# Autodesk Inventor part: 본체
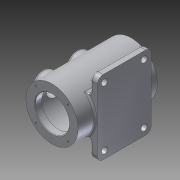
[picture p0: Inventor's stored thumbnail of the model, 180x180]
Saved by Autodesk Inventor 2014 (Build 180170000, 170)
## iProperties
Created: 2014-12
Part Number: 본체
Material: 알루미늄 6061
Document SubType Name: Modeling
Designer: Owner
Mass: 1294 g
Surface Area: 1040.12 cm^2
Volume: 477.492 cm^3
Density: 2.71 g/cm^3
Appearance: 알루미늄 - 평지
Author: Owner
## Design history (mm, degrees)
sketch "스케치1"
  geometry: C1 r 46 at (0, 0); 1 further point
  constraints: 1 centre point, 1 coincident
  dimensions: "d0" = 92 diameter of C1
extrude "돌출1" new body sketch "스케치1" stored distance "d1" = 140; taper "d2" = 0 deg
sketch "스케치2"
  geometry: C1 r 46 at (0, 0) reference; C2 r 30 at (0, 0)
  constraints: 1 centre point, 1 coincident
  dimensions: "d3" = 60 diameter of C2
extrude "돌출2" cut sketch "스케치2" distance "d4" = 12; taper "d5" = 0 deg
sketch "스케치3"
  geometry: C1 r 46 at (0, 0) reference; C2 r 30 at (0, 0)
  constraints: 1 centre point, 1 coincident
  dimensions: "d6" = 60 diameter of C2
extrude "돌출3" cut sketch "스케치3" distance "d7" = 12; taper "d8" = 0 deg
node "작업 평면2"
sketch "스케치4"
  geometry: C1 r 37.5 at (0, 0); 1 further point
  constraints: 1 centre point, 1 coincident
  dimensions: "d10" = 75 diameter of C1
extrude "돌출4" cut sketch "스케치4" stored distance "d11" = 12; taper "d12" = 0 deg
node "작업 평면3"
sketch "스케치5"
  geometry: L1 (70, -46)-(70, 46) reference; L2 (-40, 65)-(55, 65); L3 (55, 65)-(55, -65); L4 (55, -65)-(-40, -65); L5 (-40, -65)-(-40, 65); 2 further points
  constraints: 8 end point, 2 parallel, 1 horizontal, 1 horizontal alignment, 1 midpoint, 1 perpendicular
  dimensions: "d15" = 15 distance between parallel lines of L1 L3; "d16" = 130 distance between parallel lines of L4 L2; "d17" = 95 distance between parallel lines of L3 L5
extrude "돌출5" join sketch "스케치5" distance "d18" = 12; taper "d19" = 0 deg
node "작업 평면4"
sketch "스케치6"
  geometry: L1 (70, -46)-(70, 46) reference; L2 (-70, 46)-(-70, -46) reference; C1 r 20 at (30, 0); 2 further points
  constraints: 1 centre point, 1 coincident, 1 horizontal alignment
  dimensions: "d21" = 40 distance from line of L1 point (30, 0); "d22" = 40 diameter of C1
extrude "돌출6" join sketch "스케치6" stored distance "d23" = 12; taper "d24" = 0 deg
sketch "스케치7"
  geometry: L1 (-70, 46)-(-70, -46) reference; L2 (70, -46)-(70, 46) reference; C1 r 20 at (30, 0) reference; C2 r 20 at (-30, 0); 2 further points
  constraints: 1 centre point, 1 coincident, 1 horizontal alignment
  dimensions: "d25" = 60 distance of C1.centre point (-30, 0); "d26" = 40 diameter of C2
extrude "돌출7" join sketch "스케치7" stored distance "d27" = 12; taper "d28" = 0 deg
sketch "스케치8"
  geometry: C1 r 20 at (0, 0) reference; C2 r 15 at (0, 0); 1 further point
  constraints: 1 centre point, 1 coincident
  dimensions: "d29" = 30 diameter of C2
extrude "돌출8" cut sketch "스케치8" distance "d30" = 8; taper "d31" = 0 deg
sketch "스케치9"
  geometry: C1 r 20 at (0, 0) reference; C2 r 15 at (0, 0); 1 further point
  constraints: 1 centre point, 1 coincident
  dimensions: "d32" = 30 diameter of C2
extrude "돌출9" cut sketch "스케치9" distance "d33" = 8; taper "d34" = 0 deg
sketch "스케치10"
  geometry: C1 r 15 at (0, 0) reference; C2 r 12.5 at (0, 0); 1 further point
  constraints: 1 centre point, 1 coincident
  dimensions: "d35" = 25 diameter of C2
extrude "돌출10" cut sketch "스케치10" stored distance "d36" = 8; taper "d37" = 0 deg
sketch "스케치11"
  geometry: C1 r 15 at (0, 0) reference; C2 r 12.5 at (0, 0); 1 further point
  constraints: 1 centre point, 1 coincident
  dimensions: "d38" = 25 diameter of C2
extrude "돌출11" cut sketch "스케치11" stored distance "d39" = 8; taper "d40" = 0 deg
sketch "스케치12"
  geometry: L1 (0, 0)-(28.284, 28.284); L2 (0, 0)-(40, 0); C1 r 46 at (0, 0) reference; 1 further point
  constraints: 4 end point, 1 coincident, 1 equal length, 1 horizontal
  dimensions: "d41" = 40 distance of L1.start L1.end; "d42" = 45 deg angle of L2 L1
hole "구멍1" sketch "스케치12" at (28.284, 28.284) diameter "d43" = 3.242; stored, may be unused: countersink angle "d47" = 90 deg, drill point angle "d49" = 118 deg; dims "d44" = 8, "d45" = 4, "d46" = 2, "d48" = 10
fillet "모깎기1" dims "d53" = 10
sketch "스케치14"
  geometry: L1 (-25.923, 55)-(-55, 55) reference; L2 (-65, 45)-(-65, -30) reference; L3 (-55, -40)-(55, -40) reference; C1 r 5.5 at (-52, 42.5); C2 r 5.5 at (-52, -27.5); 3 further points
  constraints: 2 centre point, 2 coincident
  dimensions: "d54" = 13 distance from line of L2 point (-52, 42.5); "d55" = 12.5 distance from line of L1 point (-52, 42.5); "d56" = 11 diameter of C1; "d59" = 13 distance from line of L2 point (-52, -27.5); "d60" = 12.5 distance from line of L3 point (-52, -27.5); "d61" = 11 diameter of C2
extrude "돌출12" cut sketch "스케치14" stored distance "d57" = 8; taper "d58" = 0 deg
sketch "스케치15"
  geometry: L1 (65, -30)-(65, 45) reference; C1 r 5.5 at (52, -27.5) reference; 2 further points
  constraints: 1 other
  dimensions: "d62" = 35 vertical distance of point (57, 7.5) C1.centre; "d63" = 8 distance from line of L1 point (57, 7.5)
feature "엠보싱1" sketch "스케치15" dims "d64" = 1, "d65" = 0
fillet "모깎기2" dims "d66" = 3
fillet "모깎기3" dims "d67" = 3
chamfer "모따기1" distance "d68" = 1; stored, may be unused: second distance "d69" = 2, angle "d70" = 45 deg
chamfer "모따기2" distance "d71" = 1; stored, may be unused: second distance "d72" = 2, angle "d73" = 45 deg
fillet "모깎기4" dims "d74" = 5
fillet "모깎기5" dims "d75" = 5
fillet "모깎기6" dims "d76" = 3
fillet "모깎기7" dims "d77" = 3
fillet "모깎기8" dims "d78" = 3
node "솔리드1"
pattern_circular "원형 패턴1" dims angle "d51" = 360 deg
mirror "대칭1"
mirror "대칭2"
node "투영된 루프1"
other parameters: "d9" = 58, "d20" = -106
